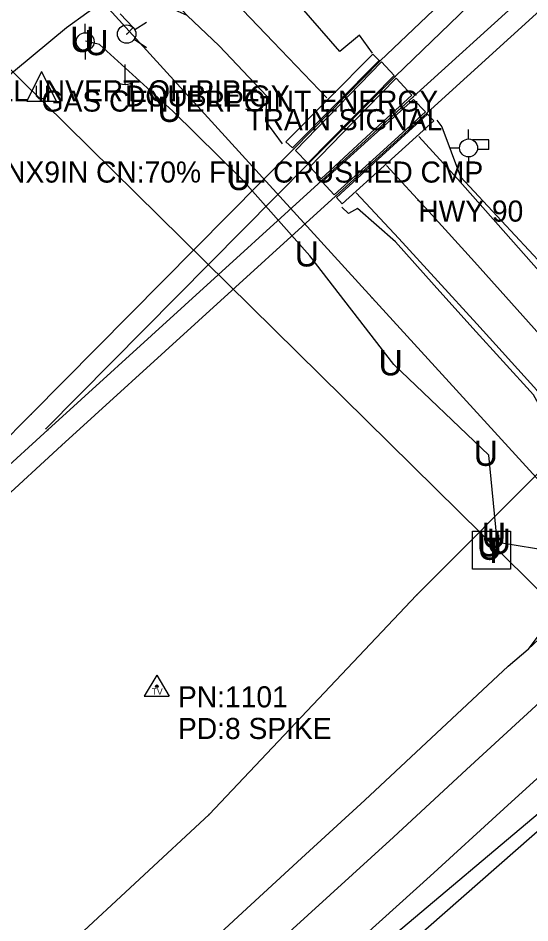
# Model space of a CAD drawing. Extents: x 1660112 to 1662239, y 668919 to 671377.
# Drawn here: x 1661444.9 to 1661566.2, y 669800.5 to 670014.9 of the extents above; entities that cross this region are included whole.
import ezdxf

# ---------------------------------------------------------------- set-up
doc = ezdxf.new("R2010")
doc.units = 0
for name, color, linetype in [('Default', 7, 'Continuous'), ('S_BASELINE', 7, 'Continuous'), ('S_EDGE_CONCRETE', 7, 'Continuous'), ('S_EDGE_PAVEMENT', 7, 'Continuous'), ('S_FIBER_OPTIC_CABLE', 7, 'Continuous'), ('S_MISC_STRUCTURES_ANNOT', 7, 'Continuous'), ('S_MSC_PT_SYM', 7, 'Continuous'), ('S_PAVEMENT_CROWN', 7, 'Continuous'), ('S_RAILROAD', 7, 'Continuous'), ('S_SANITARY_SEWER', 7, 'Continuous'), ('S_SECONDARY_CTL', 7, 'Continuous'), ('S_SECONDARY_CTL_ANNOT', 7, 'Continuous'), ('S_SHOULDER', 7, 'Continuous'), ('S_SIDE_DRAIN_ANNOT', 7, 'Continuous'), ('S_SURVEY_TEXT_ANNOT', 7, 'Continuous'), ('S_TELEPHONE_UTILITIES', 7, 'Continuous'), ('S_UNDERGROUND_CABLE', 7, 'Continuous'), ('S_UTILITY_POLE', 7, 'Continuous'), ('S_UTILITY_POLE_ANNOT', 7, 'Continuous'), ('S_UTL_PT_SYM', 7, 'Continuous'), ('S_WATER_UTILITIES', 7, 'Continuous')]:
    doc.layers.add(name, color=color, linetype=linetype)

msp = doc.modelspace()

# ---------------------------------------------------------------- linework, layer by layer
at = {"layer": 'S_BASELINE'}
msp.add_line((1661604.59, 669857.12), (1660827.54, 669202.71), dxfattribs=at)
at = {"layer": 'S_EDGE_CONCRETE'}
for points in [[(1661530.51, 670004.88), (1661528.97, 670006.37), (1661518.67, 669995.99), (1661508.37, 669985.62), (1661509.93, 669984.17), (1661520.22, 669994.53)], [(1661534.04, 670001.36), (1661523.82, 669990.98), (1661513.59, 669980.6), (1661510.64, 669983.54), (1661520.85, 669994.04), (1661531.07, 670004.54)], [(1661538.2, 669996.67), (1661527.46, 669986.77), (1661516.72, 669976.86), (1661514.03, 669979.7), (1661524.28, 669990.22), (1661534.53, 670000.74)], [(1661519.81, 669973.05), (1661517.01, 669976.14), (1661527.83, 669985.9), (1661538.65, 669995.66), (1661541.44, 669992.74), (1661530.63, 669982.89)], [(1661521.74, 669970.95), (1661520.36, 669972.41), (1661531.15, 669982.29), (1661541.93, 669992.16), (1661543.43, 669990.57), (1661532.58, 669980.76)]]:
    msp.add_lwpolyline(points, close=True, dxfattribs=at)
at = {"layer": 'S_EDGE_PAVEMENT'}
for points in [[(1661528.89, 670006.64), (1661525.81, 670010.93), (1661521.19, 670007.06), (1661512.12, 670017.42), (1661503.06, 670027.78), (1661494.14, 670038.45), (1661485.22, 670049.12), (1661475.65, 670058.13), (1661469.7, 670064.69), (1661453.26, 670082.63), (1661441.58, 670095.54), (1661429.9, 670108.45), (1661415.33, 670123.89), (1661400.76, 670139.32), (1661387.62, 670152.61), (1661374.47, 670165.9), (1661358.81, 670181.9), (1661343.14, 670197.9), (1661339.48, 670201.44), (1661329.75, 670211.05), (1661320.02, 670220.65), (1661304.77, 670236.19)], [(1661507.57, 669985.17), (1661503.63, 669990.55), (1661503.83, 669996.41), (1661492.59, 670008.33), (1661484.98, 670015.56), (1661475.91, 670025.37), (1661466.84, 670035.18), (1661454.4, 670049.73), (1661445.95, 670059), (1661437.51, 670068.28), (1661425.39, 670081.13), (1661413.28, 670093.99), (1661399.68, 670108.94), (1661386.08, 670123.89), (1661373.13, 670137.66), (1661360.18, 670151.43), (1661345.14, 670167.24), (1661330.11, 670183.04), (1661325.69, 670187.24), (1661316.74, 670196.41), (1661307.8, 670205.57), (1661291.28, 670222.16)], [(1661527.23, 669797.8), (1661542.56, 669811.61), (1661560.01, 669827.54), (1661577.47, 669843.46), (1661587.7, 669853.61), (1661602.47, 669865.64), (1661611.61, 669875.02), (1661620.74, 669884.39), (1661637.78, 669899.63), (1661645.56, 669910.14), (1661656.74, 669920.41), (1661667.92, 669930.69), (1661683.38, 669944.69), (1661698.84, 669958.7), (1661714.13, 669973.35), (1661725.28, 669983.31), (1661736.44, 669993.26), (1661746.57, 670002.69), (1661756.7, 670012.13), (1661762.09, 670016.26), (1661771.92, 670025.7), (1661786.96, 670039.58), (1661802.01, 670053.47)], [(1661484.97, 670015.57), (1661481.44, 670017.1), (1661474.37, 670019.33), (1661466.03, 670019.66), (1661456.43, 670012.6), (1661444.31, 670002.59), (1661432.19, 669992.58), (1661429.76, 669993.52), (1661418.03, 669982.83), (1661399.88, 669965.82), (1661383.18, 669950.54), (1661366.48, 669935.26), (1661355.84, 669925.69), (1661345.19, 669916.12), (1661334.54, 669906.55), (1661323.9, 669896.98), (1661314.39, 669888.26), (1661304.88, 669879.54), (1661295.37, 669870.82), (1661285.87, 669862.1), (1661271.87, 669849.3), (1661257.87, 669836.51)], [(1661539.87, 669986.88), (1661549.09, 669976.87), (1661558.69, 669965.95), (1661568.29, 669955.03), (1661580.08, 669943.31), (1661585.93, 669938.89), (1661596.24, 669933.25), (1661605.77, 669929.84), (1661617.85, 669928.83), (1661635.53, 669933.18), (1661641.44, 669936.4), (1661650.28, 669942.7)], [(1661432.01, 669741.93), (1661449.2, 669757.82), (1661461.17, 669768.88), (1661473.15, 669779.94), (1661485.12, 669791), (1661497.09, 669802.06), (1661512.08, 669815.85), (1661527.07, 669829.65), (1661544.05, 669845.51), (1661561.04, 669861.38), (1661565.83, 669865.41), (1661573.24, 669872.37), (1661579.19, 669880.3), (1661583.76, 669891.47), (1661584.04, 669901.2), (1661578.64, 669914.49), (1661567.83, 669926.75), (1661553.64, 669942.48), (1661544.41, 669952.61), (1661535.19, 669962.75), (1661525.02, 669973.56)]]:
    msp.add_lwpolyline(points, dxfattribs=at)
at = {"layer": 'S_FIBER_OPTIC_CABLE'}
for p, q in [((1661539.32, 669878.16), (1661573.33, 669912.35)), ((1661490.21, 669826.26), (1661539.32, 669878.16)), ((1661442.32, 669781.84), (1661490.21, 669826.26))]:
    msp.add_line(p, q, dxfattribs=at)
at = {"layer": 'S_MSC_PT_SYM'}
for points in [[(1661530.69, 670004.84), (1661530.69, 670004.89), (1661530.69, 670004.84), (1661530.64, 670004.84), (1661530.69, 670004.84), (1661530.69, 670004.79), (1661530.69, 670004.84), (1661530.74, 670004.84)], [(1661534.31, 670001.1), (1661534.31, 670001.15), (1661534.31, 670001.1), (1661534.26, 670001.1), (1661534.31, 670001.1), (1661534.31, 670001.05), (1661534.31, 670001.1), (1661534.36, 670001.1)], [(1661538.56, 669996.25), (1661538.56, 669996.3), (1661538.56, 669996.25), (1661538.51, 669996.25), (1661538.56, 669996.25), (1661538.56, 669996.2), (1661538.56, 669996.25), (1661538.61, 669996.25)], [(1661499.01, 669993.37), (1661499.01, 669993.42), (1661499.01, 669993.37), (1661498.96, 669993.37), (1661499.01, 669993.37), (1661499.01, 669993.32), (1661499.01, 669993.37), (1661499.06, 669993.37)], [(1661541.88, 669992.49), (1661541.88, 669992.54), (1661541.88, 669992.49), (1661541.83, 669992.49), (1661541.88, 669992.49), (1661541.88, 669992.44), (1661541.88, 669992.49), (1661541.93, 669992.49)], [(1661510.24, 669983.94), (1661510.24, 669983.99), (1661510.24, 669983.94), (1661510.19, 669983.94), (1661510.24, 669983.94), (1661510.24, 669983.89), (1661510.24, 669983.94), (1661510.29, 669983.94)], [(1661513.66, 669980.37), (1661513.66, 669980.42), (1661513.66, 669980.37), (1661513.61, 669980.37), (1661513.66, 669980.37), (1661513.66, 669980.32), (1661513.66, 669980.37), (1661513.71, 669980.37)], [(1661516.9, 669976.45), (1661516.9, 669976.5), (1661516.9, 669976.45), (1661516.85, 669976.45), (1661516.9, 669976.45), (1661516.9, 669976.4), (1661516.9, 669976.45), (1661516.95, 669976.45)], [(1661520.12, 669972.73), (1661520.12, 669972.78), (1661520.12, 669972.73), (1661520.07, 669972.73), (1661520.12, 669972.73), (1661520.12, 669972.68), (1661520.12, 669972.73), (1661520.17, 669972.73)], [(1661539.75, 669971.71), (1661539.75, 669971.76), (1661539.75, 669971.71), (1661539.7, 669971.71), (1661539.75, 669971.71), (1661539.75, 669971.66), (1661539.75, 669971.71), (1661539.8, 669971.71)], [(1661448.04, 669921.07), (1661448.04, 669921.12), (1661448.04, 669921.07), (1661447.98, 669921.07), (1661448.04, 669921.07), (1661448.04, 669921.02), (1661448.04, 669921.07), (1661448.08, 669921.07)], [(1661451.52, 669917.63), (1661451.52, 669917.68), (1661451.52, 669917.63), (1661451.47, 669917.63), (1661451.52, 669917.63), (1661451.52, 669917.58), (1661451.52, 669917.63), (1661451.57, 669917.63)], [(1661451.97, 669917.34), (1661451.97, 669917.39), (1661451.97, 669917.34), (1661451.92, 669917.34), (1661451.97, 669917.34), (1661451.97, 669917.29), (1661451.97, 669917.34), (1661452.02, 669917.34)], [(1661455.22, 669913.63), (1661455.22, 669913.68), (1661455.22, 669913.63), (1661455.17, 669913.63), (1661455.22, 669913.63), (1661455.22, 669913.58), (1661455.22, 669913.63), (1661455.27, 669913.63)]]:
    msp.add_lwpolyline(points, dxfattribs=at)
at = {"layer": 'S_PAVEMENT_CROWN'}
for points in [[(1661518.06, 669996.03), (1661505.4, 670009.31), (1661492.74, 670022.59), (1661480.19, 670036.99), (1661467.64, 670051.39), (1661473.76, 670044.39), (1661461.34, 670057.98), (1661445.4, 670075.38), (1661443.99, 670076.39), (1661432.69, 670088.65), (1661421.39, 670100.9), (1661407.48, 670115.88), (1661393.57, 670130.85), (1661380.41, 670144.59), (1661367.25, 670158.33), (1661351.88, 670174.26), (1661336.51, 670190.18), (1661332.38, 670194.36), (1661323.21, 670203.51), (1661314.05, 670212.66), (1661297.56, 670228.68)], [(1661503.87, 669793.54), (1661518.86, 669807.19), (1661533.86, 669820.84), (1661551.21, 669836.85), (1661568.55, 669852.86), (1661579.03, 669862.68), (1661589.51, 669872.49), (1661600, 669882.3), (1661610.48, 669892.12), (1661619.87, 669900.79), (1661629.26, 669909.46), (1661638.66, 669918.13), (1661648.05, 669926.8), (1661660.37, 669938.02), (1661678.3, 669954.58), (1661696.23, 669971.14), (1661712.97, 669986.61)], [(1661532.25, 669980.05), (1661542.23, 669969.08), (1661553.09, 669957.19), (1661563.16, 669945.92), (1661573.22, 669934.64), (1661588.29, 669917.36), (1661603.37, 669900.08)]]:
    msp.add_lwpolyline(points, dxfattribs=at)
at = {"layer": 'S_RAILROAD'}
for p, q in [((1661530.69, 670004.84), (1661583.12, 670054.69)), ((1661534.31, 670001.1), (1661586.39, 670051.53)), ((1661538.56, 669996.25), (1661592.63, 670045.46)), ((1661541.88, 669992.49), (1661596.12, 670041.9)), ((1661510.24, 669983.94), (1661530.69, 670004.84)), ((1661513.66, 669980.37), (1661534.31, 670001.1)), ((1661516.9, 669976.45), (1661538.56, 669996.25)), ((1661520.12, 669972.73), (1661541.88, 669992.49)), ((1661551.67, 669986.28), (1661551.67, 669988.53)), ((1661556.48, 669986.13), (1661552.6, 669986.13)), ((1661556.48, 669983.8), (1661556.48, 669986.13)), ((1661448.04, 669921.07), (1661510.24, 669983.94)), ((1661549.58, 669984.15), (1661547.25, 669984.15)), ((1661556.48, 669983.8), (1661553.76, 669983.8)), ((1661551.75, 669979.74), (1661551.75, 669982.06)), ((1661451.52, 669917.63), (1661513.66, 669980.37)), ((1661451.97, 669917.34), (1661516.9, 669976.45)), ((1661455.22, 669913.63), (1661520.12, 669972.73)), ((1661397.52, 669870.6), (1661448.04, 669921.07)), ((1661398.98, 669869.07), (1661451.97, 669917.34)), ((1661402.43, 669865.48), (1661455.22, 669913.63))]:
    msp.add_line(p, q, dxfattribs=at)
msp.add_circle((1661551.67, 669984.17), 2.13, dxfattribs=at)
at = {"layer": 'S_SANITARY_SEWER'}
msp.add_line((1661704.02, 669745.54), (1661292.91, 670150.69), dxfattribs=at)
at = {"layer": 'S_SECONDARY_CTL'}
for p, q in [((1661477.81, 669859.22), (1661474.8, 669854.27)), ((1661477.81, 669859.22), (1661480.76, 669854.27)), ((1661474.8, 669854.27), (1661480.76, 669854.27))]:
    msp.add_line(p, q, dxfattribs=at)
for radius in [0.311, 0.183, 0.103]:
    msp.add_circle((1661477.81, 669856.61), radius, dxfattribs=at)
at = {"layer": 'S_SHOULDER'}
for points in [[(1661544.18, 669990.78), (1661545.38, 669989.16), (1661549.73, 669977.29), (1661559.45, 669966.88), (1661569.17, 669956.48), (1661581.29, 669945.51), (1661587.1, 669939.82), (1661596.61, 669934.16), (1661606.09, 669931.97), (1661618.1, 669932.69), (1661634.83, 669936.71), (1661634.11, 669936.74), (1661641.01, 669939.29), (1661649.51, 669944.11), (1661652.54, 669946.88), (1661670.8, 669962.78), (1661689.06, 669978.67), (1661705.8, 669994.5), (1661722.55, 670010.32)], [(1661565.9, 669865.41), (1661571.88, 669873.46), (1661576.91, 669881.7), (1661580, 669892.53), (1661579.44, 669899.68), (1661574.75, 669911.86), (1661567.03, 669925.66), (1661552.68, 669941.47), (1661543.51, 669951.68), (1661534.34, 669961.89), (1661525.37, 669969.85), (1661523.19, 669968.6), (1661521.62, 669970.1)]]:
    msp.add_lwpolyline(points, dxfattribs=at)
at = {"layer": 'S_TELEPHONE_UTILITIES'}
msp.add_lwpolyline([(1661552.58, 669884.35), (1661552.58, 669893.35), (1661561.58, 669893.35), (1661561.58, 669884.35)], close=True, dxfattribs=at)
at = {"layer": 'S_UNDERGROUND_CABLE'}
for p, q in [((1661464.23, 670008.69), (1661460.87, 670009.46)), ((1661481.59, 669992.88), (1661464.23, 670008.69)), ((1661450.49, 670002.31), (1661446.96, 669995.22)), ((1661450.49, 670002.31), (1661453.97, 669995.22)), ((1661449.29, 669996.46), (1661449.29, 669998.9)), ((1661451.65, 669998.9), (1661451.65, 669996.46)), ((1661446.96, 669995.22), (1661453.97, 669995.22)), ((1661449.91, 669995.8), (1661449.29, 669996.46)), ((1661451.11, 669995.8), (1661449.91, 669995.8)), ((1661451.65, 669996.46), (1661451.11, 669995.8)), ((1661498.03, 669976.72), (1661481.59, 669992.88)), ((1661514.09, 669958.62), (1661498.03, 669976.72)), ((1661533.95, 669932.83), (1661514.09, 669958.62)), ((1661556.51, 669911.39), (1661533.95, 669932.83)), ((1661558.41, 669891.9), (1661556.51, 669911.39)), ((1661557.24, 669889.94), (1661558.41, 669891.9)), ((1661559.59, 669890.51), (1661557.43, 669889.12)), ((1661577.17, 669887.67), (1661559.59, 669890.51))]:
    msp.add_line(p, q, dxfattribs=at)
at = {"layer": 'S_UTILITY_POLE'}
for p, q in [((1661460.79, 670011.43), (1661460.79, 670013.56)), ((1661460.79, 670007.21), (1661460.79, 670005.16)), ((1661470.24, 670003.94), (1661470.24, 669999.21))]:
    msp.add_line(p, q, dxfattribs=at)
msp.add_circle((1661460.82, 670009.35), 2.11, dxfattribs=at)
msp.add_arc((1661470.31, 670002.63), 3.41, 226.3972, 313.6028, dxfattribs=at)
at = {"layer": 'S_UTL_PT_SYM'}
for points in [[(1661472.19, 670012.72), (1661472.19, 670012.77), (1661472.19, 670012.72), (1661472.14, 670012.72), (1661472.19, 670012.72), (1661472.19, 670012.67), (1661472.19, 670012.72), (1661472.24, 670012.72)], [(1661472.2, 670012.7), (1661472.2, 670012.75), (1661472.2, 670012.7), (1661472.15, 670012.7), (1661472.2, 670012.7), (1661472.2, 670012.65), (1661472.2, 670012.7), (1661472.25, 670012.7)], [(1661470.66, 670011.15), (1661470.66, 670011.2), (1661470.66, 670011.15), (1661470.61, 670011.15), (1661470.66, 670011.15), (1661470.66, 670011.1), (1661470.66, 670011.15), (1661470.71, 670011.15)], [(1661528.82, 669948.66), (1661528.82, 669948.71), (1661528.82, 669948.66), (1661528.77, 669948.66), (1661528.82, 669948.66), (1661528.82, 669948.61), (1661528.82, 669948.66), (1661528.87, 669948.66)], [(1661539.32, 669878.16), (1661539.32, 669878.21), (1661539.32, 669878.16), (1661539.27, 669878.16), (1661539.32, 669878.16), (1661539.32, 669878.11), (1661539.32, 669878.16), (1661539.37, 669878.16)], [(1661490.21, 669826.26), (1661490.21, 669826.31), (1661490.21, 669826.26), (1661490.16, 669826.26), (1661490.21, 669826.26), (1661490.21, 669826.21), (1661490.21, 669826.26), (1661490.26, 669826.26)]]:
    msp.add_lwpolyline(points, dxfattribs=at)
at = {"layer": 'S_WATER_UTILITIES'}
for p, q in [((1661528.82, 669948.66), (1661452.55, 670032.39)), ((1661472.2, 670012.7), (1661469.14, 670015.98)), ((1661472.55, 670012.22), (1661475.37, 670013.95)), ((1661472.19, 670012.72), (1661470.66, 670011.15)), ((1661472.43, 670009.91), (1661475.34, 670007.98)), ((1661569.45, 669904.22), (1661528.82, 669948.66)), ((1661610.79, 669859.67), (1661522.71, 669782.51))]:
    msp.add_line(p, q, dxfattribs=at)
msp.add_circle((1661470.65, 670011.16), 2.18, dxfattribs=at)

# ---------------------------------------------------------------- texts
at = {"layer": 'Default'}
for p in [(1661457.24, 670006.91), (1661460.6, 670006.15), (1661477.96, 669990.33), (1661494.4, 669974.18), (1661510.46, 669956.08), (1661530.32, 669930.28), (1661552.88, 669908.84), (1661554.78, 669889.36), (1661555.96, 669887.96), (1661553.61, 669887.39), (1661553.8, 669886.57)]:
    msp.add_text('U', height=6, rotation=360, dxfattribs=at).set_placement(p)
at = {"layer": 'S_MISC_STRUCTURES_ANNOT'}
msp.add_text('TRAIN SIGNAL', height=5, dxfattribs=at).set_placement((1661499.01, 669988.37))
at = {"layer": 'S_SECONDARY_CTL'}
msp.add_text('TV', height=1.5, rotation=360, dxfattribs=at).set_placement((1661476.61, 669854.6))
at = {"layer": 'S_SECONDARY_CTL_ANNOT'}
for s, p in [('PN:1101', (1661482.81, 669851.61)), ('PD:8 SPIKE', (1661482.81, 669844.11))]:
    msp.add_text(s, height=5, dxfattribs=at).set_placement(p)
at = {"layer": 'S_SIDE_DRAIN_ANNOT'}
for s, p in [('CN:70% FILL INVERT OF PIPE', (1661407.39, 669995.2)), ('DI:20INX9IN CN:70% FILL CRUSHED CMP', (1661424, 669975.96))]:
    msp.add_text(s, height=5, dxfattribs=at).set_placement(p)
at = {"layer": 'S_SURVEY_TEXT_ANNOT'}
msp.add_text('HWY 90', height=5, dxfattribs=at).set_placement((1661539.75, 669966.71))
at = {"layer": 'S_TELEPHONE_UTILITIES'}
msp.add_text('T', height=6, rotation=360, dxfattribs=at).set_placement((1661555.14, 669885.85))
at = {"layer": 'S_UTILITY_POLE_ANNOT'}
for s, p in [('DOUBLE GY', (1661470.26, 669993.99)), ('GAS CENTERPOINT ENERGY', (1661450.49, 669992.78))]:
    msp.add_text(s, height=5, dxfattribs=at).set_placement(p)

doc.saveas('drawing.dxf')
